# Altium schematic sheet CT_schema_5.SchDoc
size 511 x 385 mm
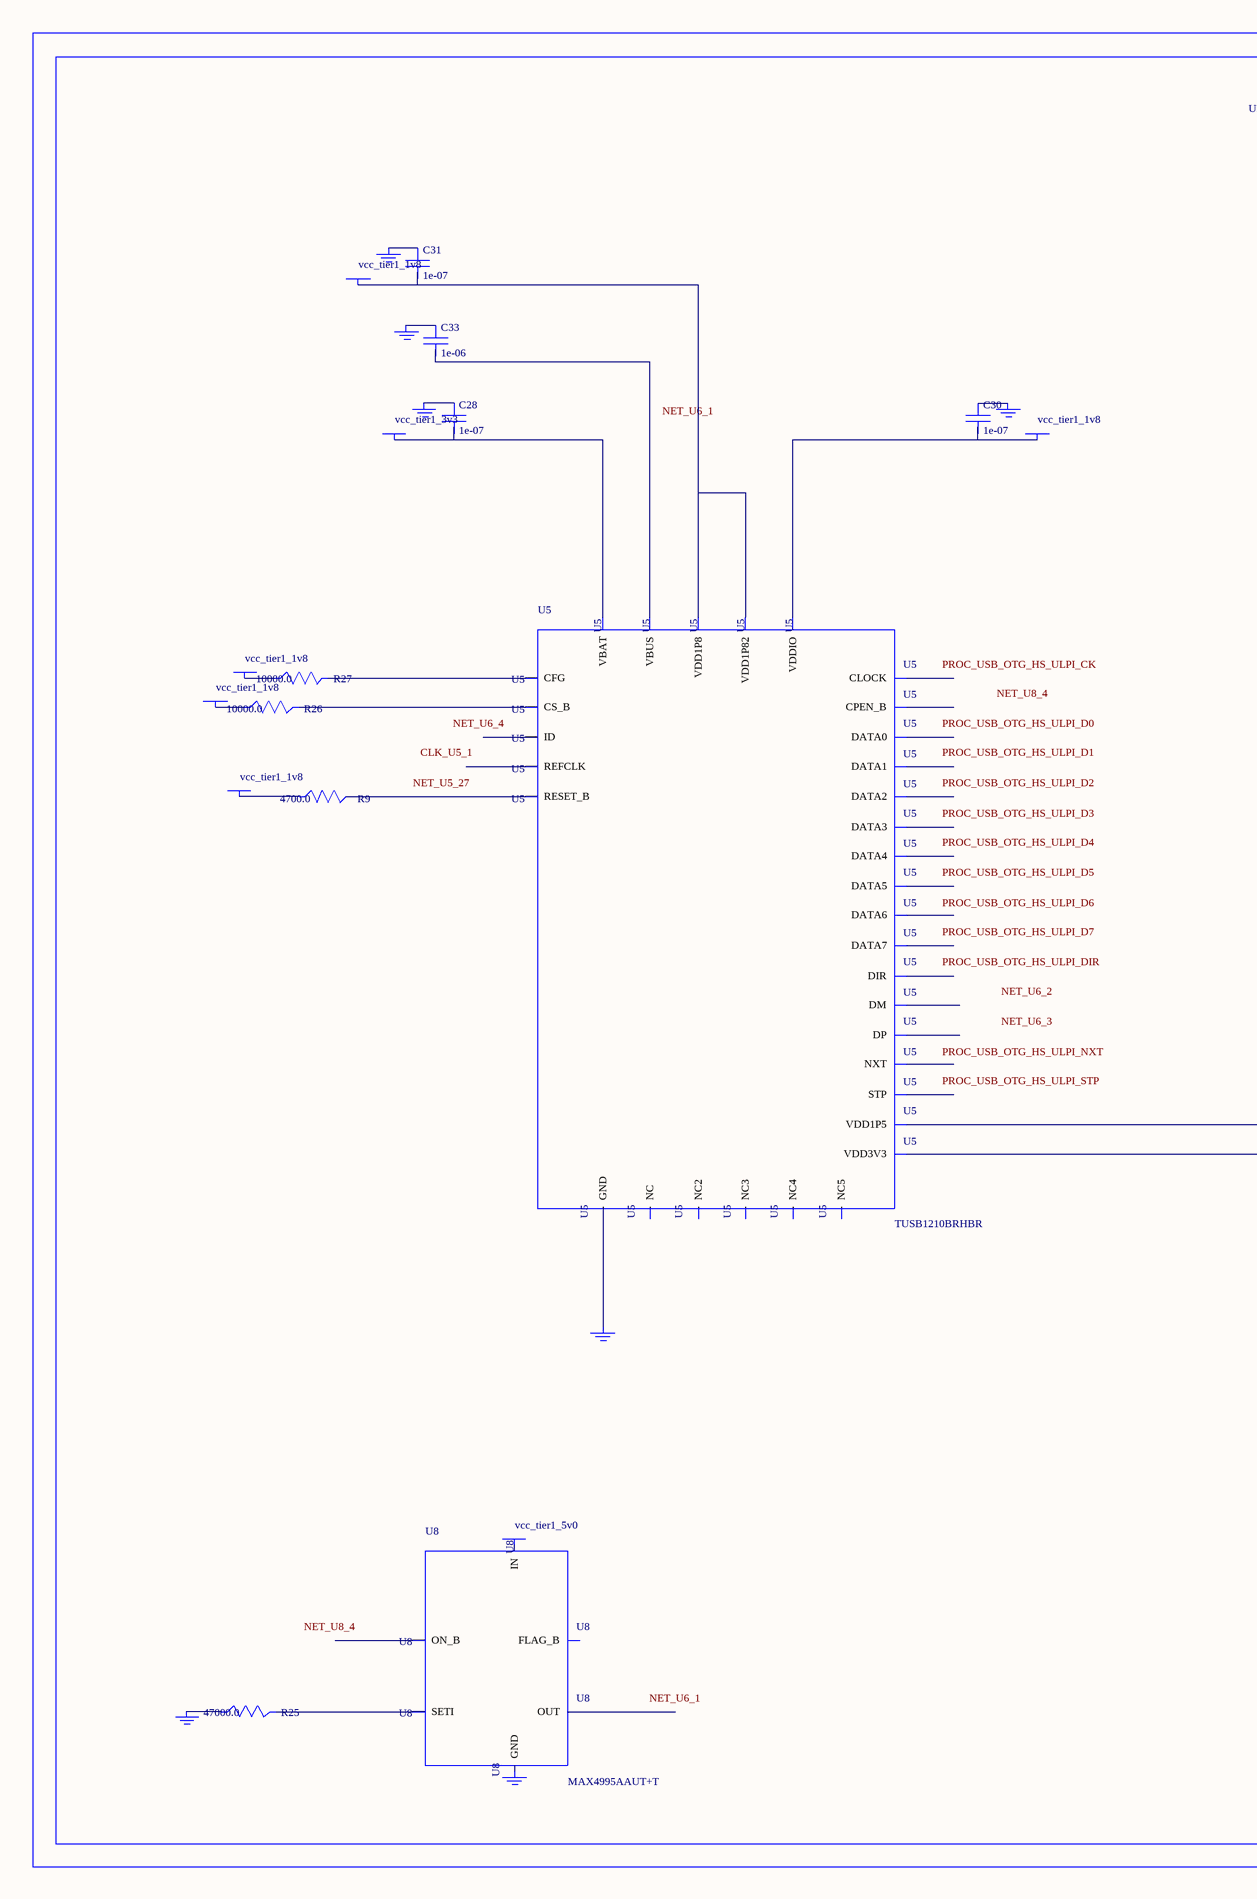
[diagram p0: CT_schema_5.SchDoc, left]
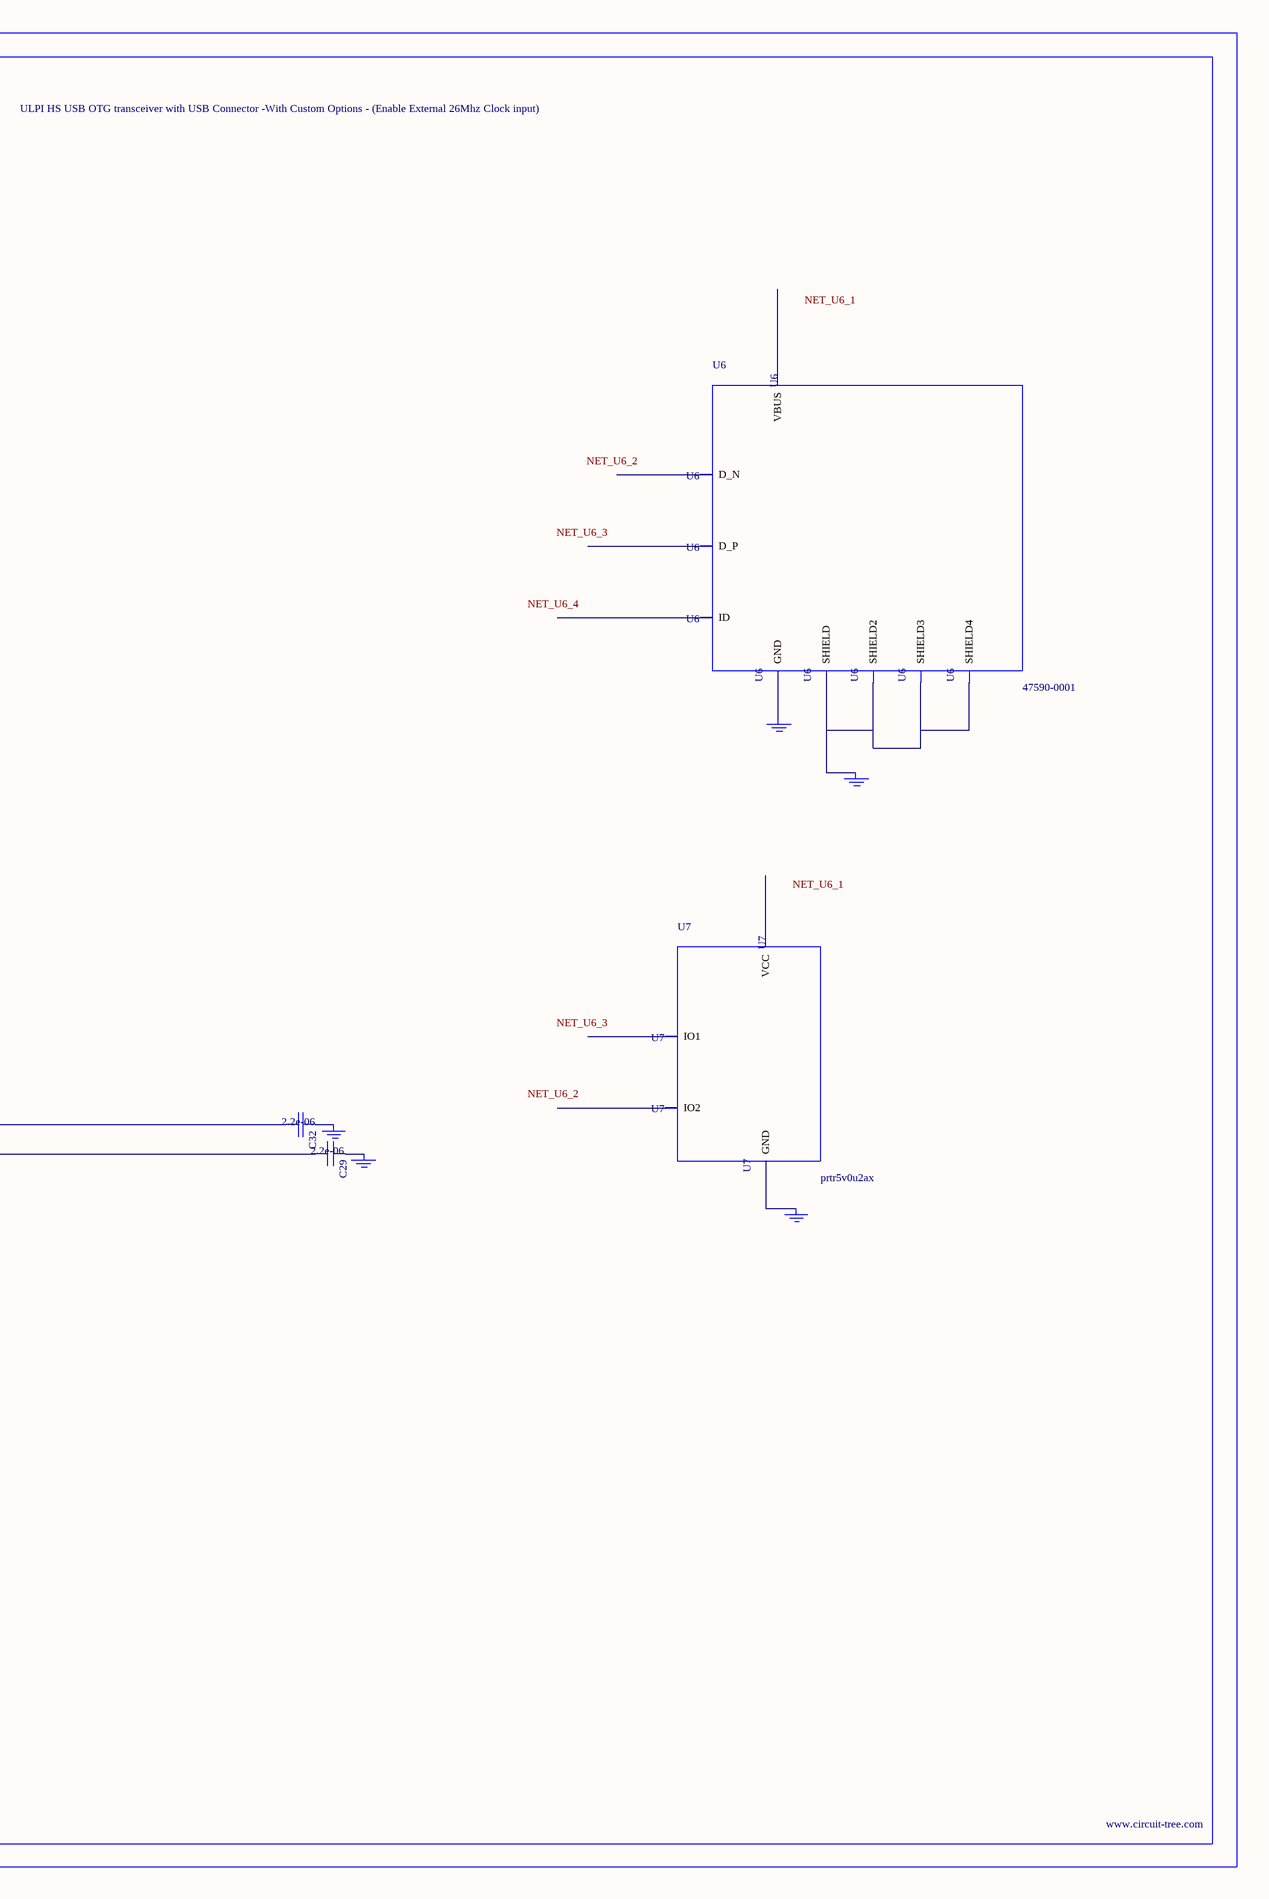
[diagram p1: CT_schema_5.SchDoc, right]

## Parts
BORDER4  (no value)
C28  1e-07  [C0402]
C29  2.2e-06  [C0603]
C30  1e-07  [C0402]
C31  1e-07  [C0402]
C32  2.2e-06  [C0603]
C33  1e-06  [C0603]
GND_INSTANCE_4_0  (no value)
GND_INSTANCE_4_1  (no value)
GND_INSTANCE_4_2  (no value)
GND_INSTANCE_4_3  (no value)
GND_INSTANCE_4_4  (no value)
GND_INSTANCE_4_5  (no value)
GND_INSTANCE_4_6  (no value)
GND_INSTANCE_4_7  (no value)
GND_INSTANCE_4_8  (no value)
GND_INSTANCE_4_9  (no value)
GND_INSTANCE_4_10  (no value)
GND_INSTANCE_4_11  (no value)
POWER_INSTANCE_4_0  vcc_tier1_1v8
POWER_INSTANCE_4_1  vcc_tier1_1v8
POWER_INSTANCE_4_2  vcc_tier1_3v3
POWER_INSTANCE_4_3  vcc_tier1_1v8
POWER_INSTANCE_4_4  vcc_tier1_1v8
POWER_INSTANCE_4_5  vcc_tier1_1v8
POWER_INSTANCE_4_6  vcc_tier1_5v0
R9  4700.0  [R0603]
R25  47000.0  [R0603]
R26  10000.0  [R0603]
R27  10000.0  [R0603]
U5  TUSB1210BRHBR  [RHB32_3P45X3P45]
U6  47590-0001  [MICRO_USB_AB]
U7  prtr5v0u2ax  [SOT143B]
U8  MAX4995AAUT+T  [SOT-23-6]

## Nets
NetC28_1: C28.1 GND_INSTANCE_4_2.0(GND)
NetC28_2: C28.2 POWER_INSTANCE_4_2.0(PWR) U5.21(VBAT)
NetC29_1: C29.1 GND_INSTANCE_4_1.0(GND)
NetC29_2: C29.2 U5.20(VDD3V3)
NetC30_1: C30.1 GND_INSTANCE_4_5.0(GND)
NetC30_2: C30.2 POWER_INSTANCE_4_4.0(PWR) U5.32(VDDIO)
NetC31_1: C31.1 GND_INSTANCE_4_4.0(GND)
NetC31_2: C31.2 POWER_INSTANCE_4_3.0(PWR) U5.28(VDD1P8) U5.30(VDD1P82)
NetC32_1: C32.1 GND_INSTANCE_4_0.0(GND)
NetC32_2: C32.2 U5.12(VDD1P5)
NetC33_1: C33.1 GND_INSTANCE_4_3.0(GND)
NetC33_2: C33.2 U5.22(VBUS)
NetGND_INSTANCE_4_6_0: GND_INSTANCE_4_6.0(GND) U5.33(GND)
NetGND_INSTANCE_4_7_0: GND_INSTANCE_4_7.0(GND) U6.6(SHIELD) U6.7(SHIELD2) U6.8(SHIELD3) U6.9(SHIELD4)
NetGND_INSTANCE_4_8_0: GND_INSTANCE_4_8.0(GND) U6.5(GND)
NetGND_INSTANCE_4_9_0: GND_INSTANCE_4_9.0(GND) U7.1(GND)
NetGND_INSTANCE_4_10_0: GND_INSTANCE_4_10.0(GND) R25.1
NetPOWER_INSTANCE_4_0_0: POWER_INSTANCE_4_0.0(PWR) R26.1
NetPOWER_INSTANCE_4_1_0: POWER_INSTANCE_4_1.0(PWR) R27.1
NetPOWER_INSTANCE_4_5_0: POWER_INSTANCE_4_5.0(PWR) R9.1
NetR9_2: R9.2 U5.27(RESET_B)
NetR25_2: R25.2 U8.3(SETI)
NetR26_2: R26.2 U5.11(CS_B)
NetR27_2: R27.2 U5.14(CFG)

Not connected (* = marked no-connect by the designer): GND_INSTANCE_4_11 0(GND); POWER_INSTANCE_4_6 0(PWR); U5 1(REFCLK) 2(NXT) 3(DATA0) 4(DATA1) 5(DATA2) 6(DATA3) 7(DATA4) 8(NC) 9(DATA5) 10(DATA6) 13(DATA7) 15(NC2) 16(NC3) 17(CPEN_B) 18(DP) 19(DM) 23(ID) 24(NC4) 25(NC5) 26(CLOCK) 29(STP) 31(DIR); U6 1(VBUS) 2(D_N) 3(D_P) 4(ID); U7 2(IO1) 3(IO2) 4(VCC); U8 1(OUT) 2(GND) 4(ON_B) 5(IN) 6(FLAG_B)

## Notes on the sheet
- Labels drawn without touching a wire or pin: CLK_U5_1, NET_U5_27, NET_U6_1, NET_U6_2, NET_U6_3, NET_U6_4, NET_U8_4, PROC_USB_OTG_HS_ULPI_CK, PROC_USB_OTG_HS_ULPI_D0, PROC_USB_OTG_HS_ULPI_D1, PROC_USB_OTG_HS_ULPI_D2, PROC_USB_OTG_HS_ULPI_D3, PROC_USB_OTG_HS_ULPI_D4, PROC_USB_OTG_HS_ULPI_D5, PROC_USB_OTG_HS_ULPI_D6, PROC_USB_OTG_HS_ULPI_D7, PROC_USB_OTG_HS_ULPI_DIR, PROC_USB_OTG_HS_ULPI_NXT, PROC_USB_OTG_HS_ULPI_STP

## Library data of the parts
BORDER4 = BORDER_PAGE4
C28 C30 C31 = C0402C104K3RACTU
C29 C32 = C0603C225K8RACTU
C33 = C0603C105K3RACTU
GND_INSTANCE_4_0-GND_INSTANCE_4_11 = GND
POWER_INSTANCE_4_0-POWER_INSTANCE_4_6 = PWR
R9 = RC0603JR-074K7L
R25 = RC0603JR-0747KL
R26 R27 = RC0603JR-0710KL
